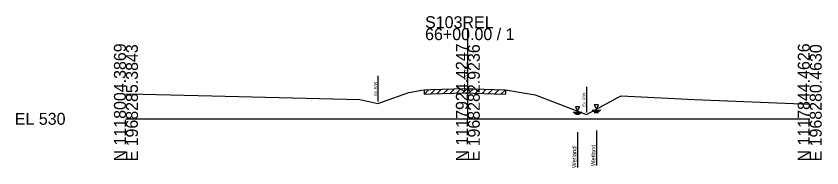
# Model space of a CAD drawing. Extents: x -26 to 163, y -10 to 24518.
# Drawn here: x -25.7 to 162.8, y 14488.5 to 14524.1 of the extents above; entities that cross this region are included whole.
import ezdxf

# ---------------------------------------------------------------- set-up
doc = ezdxf.new("R2010")
doc.units = 0
for name, color, linetype in [('RD_GPK_XS_Cell', 7, 'Continuous'), ('RD_XS_ExGround', 7, 'Continuous'), ('RD_XS_ExPaveRet', 7, 'Continuous'), ('RD_XS_ExRW', 7, 'Continuous'), ('RD_XS_EXWetland', 7, 'Continuous'), ('RD_XS_TX_Elev_EX', 7, 'Continuous')]:
    doc.layers.add(name, color=color, linetype=linetype)

msp = doc.modelspace()

# ---------------------------------------------------------------- linework, layer by layer
at = {"layer": 'RD_GPK_XS_Cell'}
for p, q in [((80, 14500), (80, 14521.26)), ((0, 14500), (80, 14500)), ((80, 14500), (160, 14500))]:
    msp.add_line(p, q, dxfattribs=at)
at = {"layer": 'RD_XS_ExGround'}
msp.add_lwpolyline([(0, 14505.89), (3.96, 14505.8), (20.08, 14505.37), (54.71, 14504.55), (55.4, 14504.4), (58.97, 14503.56), (60.07, 14503.96), (66.2, 14506.2), (69.22, 14506.7), (69.83, 14506.8), (71.34, 14506.85), (79.37, 14507.09), (80, 14507.07), (81.14, 14507.03), (88.82, 14506.81), (94.79, 14505.8), (95.77, 14505.62), (106.49, 14501.51), (107.76, 14501), (115.11, 14504.97), (115.9, 14505.4), (133.04, 14504.51), (160, 14503.43)], dxfattribs=at)
at = {"layer": 'RD_XS_ExPaveRet'}
for p, q in [((69.83, 14505.8), (70.86, 14506.84)), ((69.83, 14505.8), (69.83, 14506.8)), ((69.83, 14505.8), (71.34, 14505.85)), ((71.33, 14505.85), (72.36, 14506.88)), ((71.34, 14505.85), (79.37, 14506.09)), ((72.83, 14505.9), (73.86, 14506.93)), ((74.33, 14505.94), (75.36, 14506.97)), ((75.83, 14505.98), (76.86, 14507.01)), ((77.33, 14506.03), (78.36, 14507.06)), ((78.83, 14506.07), (79.83, 14507.07)), ((79.37, 14506.09), (80, 14506.07)), ((80, 14506.07), (81.14, 14506.03)), ((80.33, 14506.06), (81.3, 14507.03)), ((81.14, 14506.03), (88.82, 14505.81)), ((81.83, 14506.01), (82.8, 14506.98)), ((83.33, 14505.97), (84.3, 14506.94)), ((84.83, 14505.92), (85.8, 14506.9)), ((86.33, 14505.88), (87.3, 14506.85)), ((87.83, 14505.84), (88.8, 14506.81)), ((88.82, 14506.81), (88.82, 14505.81))]:
    msp.add_line(p, q, dxfattribs=at)
at = {"layer": 'RD_XS_ExRW'}
for p, q in [((58.97, 14510.06), (58.97, 14504.06)), ((107.75, 14507.51), (107.75, 14501.51))]:
    msp.add_line(p, q, dxfattribs=at)
at = {"layer": 'RD_XS_EXWetland'}
for p, q in [((105.16, 14502.83), (105.66, 14501.83)), ((106.16, 14502.83), (105.16, 14502.83)), ((105.16, 14502.83), (105.66, 14501.83)), ((106.16, 14502.83), (105.16, 14502.83)), ((105.66, 14501.83), (106.16, 14502.83)), ((105.66, 14501.83), (106.16, 14502.83)), ((109.09, 14502.01), (111.09, 14502.01)), ((109.09, 14502.01), (111.09, 14502.01)), ((109.59, 14503.26), (110.09, 14502.26)), ((110.59, 14503.26), (109.59, 14503.26)), ((109.59, 14503.26), (110.09, 14502.26)), ((110.59, 14503.26), (109.59, 14503.26)), ((110.09, 14502.26), (110.59, 14503.26)), ((110.09, 14502.26), (110.59, 14503.26)), ((104.66, 14501.58), (106.66, 14501.58)), ((104.66, 14501.58), (106.66, 14501.58)), ((104.91, 14501.33), (106.41, 14501.33)), ((104.91, 14501.33), (106.41, 14501.33)), ((105.16, 14501.08), (106.16, 14501.08)), ((105.16, 14501.08), (106.16, 14501.08)), ((109.34, 14501.76), (110.84, 14501.76)), ((109.34, 14501.76), (110.84, 14501.76)), ((109.59, 14501.51), (110.59, 14501.51)), ((109.59, 14501.51), (110.59, 14501.51)), ((105.66, 14496.83), (105.66, 14488.58)), ((105.66, 14496.83), (105.66, 14488.58)), ((110.09, 14497.26), (110.09, 14489.01)), ((110.09, 14497.26), (110.09, 14489.01))]:
    msp.add_line(p, q, dxfattribs=at)

# ---------------------------------------------------------------- texts
at = {"layer": 'RD_GPK_XS_Cell'}
for s, p in [('S103REL', (70, 14521.26)), ('66+00.00 / 1', (70, 14518.46)), ('EL 530', (-26, 14498.6))]:
    msp.add_text(s, height=2.8, dxfattribs=at).set_placement(p)
for s, p in [('N 1118004.3869', (0, 14490)), ('E 1968285.3843', (2.8, 14490)), ('N 1117924.4247', (80, 14490)), ('E 1968282.9236', (82.8, 14490)), ('N 1117844.4626', (160, 14490)), ('E 1968280.4630', (162.8, 14490))]:
    msp.add_text(s, height=2.8, rotation=90, dxfattribs=at).set_placement(p)
at = {"layer": 'RD_XS_ExRW'}
for p in [(58.72, 14505.4), (107.5, 14502.85)]:
    msp.add_text('Ex. R/W ', height=0.65, rotation=90, dxfattribs=at).set_placement(p)
at = {"layer": 'RD_XS_EXWetland'}
for p in [(105.41, 14488.47), (105.41, 14488.47), (109.84, 14488.9), (109.84, 14488.9)]:
    msp.add_text('Wetland ', height=1, rotation=90, dxfattribs=at).set_placement(p)
at = {"layer": 'RD_XS_TX_Elev_EX'}
msp.add_text('537.07', height=0.8, rotation=90, dxfattribs=at).set_placement((79.9, 14509.07))

doc.saveas('drawing.dxf')
